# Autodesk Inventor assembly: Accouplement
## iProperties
Shininess: 64.0
Length Units: 11269
Angle Units: 11279
Time Units: 11290
Mass Units: 11283
Length Display Precision: 3
Angle Display Precision: 2
Compacted: True
Created: 2003-05
Part Number: Accouplement
Document SubType Name: Assembly
Designer: Philippe
Density: 0.0
Volumn: 0.0
Area: 0.0
PropertySet Name: Model Information
Control State: 0
Master: False
Checked Out: False
Author: Philippe
